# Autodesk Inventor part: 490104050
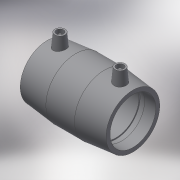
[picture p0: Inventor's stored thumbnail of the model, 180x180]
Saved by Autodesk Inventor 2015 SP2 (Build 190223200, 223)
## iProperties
Created: 2017-06
Part Number: 490104050
Material: Generic
Description: PLASSON COUPLER 50-50
Document SubType Name: Modeling
Designer: KIM
Mass: 139.695 g
Surface Area: 421.345 cm^2
Volume: 139.695 cm^3
Density: 1 g/cm^3
Appearance: Default
Author: KIM
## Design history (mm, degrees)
derived "490104.ipt"
feature "Solid1::490104.ipt"
tag "TaggingFeature1"
body "Solid1"
other parameters: "d0" = 101, "d2" = 67, "d3" = 49, "d4" = 33.66667, "d5" = 60.3, "d6" = 47.5, "d8" = 168 deg, "d10" = 19.6, "d11" = 6.53333, "d13" = 101, "d14" = 17.6296, "d15" = 49, "d16" = 49, "d17" = 47.5, "d19" = 3.52592, "d20" = 168 deg, "d22" = 62.98, "d23" = 67, "d24" = 61.0906, "d25" = 135 deg, "d26" = 40.4, "d27" = 135 deg, "d29" = 51, "d30" = 14, "d31" = 35.35, "d34" = 5 deg, "d35" = 15, "d39" = 5 deg, "d41" = 4, "d42" = 14, "d43" = 0, "d45" = 4, "d46" = 14, "d47" = 0, "d48" = 3, "d49" = 0, "d50" = 3, "d51" = 0, "d52" = 14.21, "d53" = 3.5525, "L_" = 101, "L_1" = 49, "D_" = 67, "A_" = 51, "d_2" = 12
